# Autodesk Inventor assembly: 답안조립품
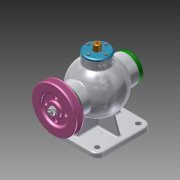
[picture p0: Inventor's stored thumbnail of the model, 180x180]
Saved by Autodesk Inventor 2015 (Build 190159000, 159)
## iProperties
Created: 2025-08
Part Number: 답안조립품
Document SubType Name: Assembly
Designer: USER
Author: USER
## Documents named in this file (16)
- C:\Users\USER\Desktop\750808V1007\답안조립품.iam
- C:\Users\USER\Desktop\750808V1007\본체.ipt
- C:\Users\USER\Desktop\750808V1007\가져온 구성요소\V-벨트풀리\V-벨트풀리.ipt
- C:\Users\USER\Desktop\750808V1007\가져온 구성요소\너트 M8\너트 M8.ipt
- C:\Users\USER\Desktop\750808V1007\가져온 구성요소\뒤커버\뒤커버.ipt
- C:\Users\USER\Desktop\750808V1007\가져온 구성요소\베어링- 6202\베어링- 6202.ipt
- C:\Users\USER\Desktop\750808V1007\가져온 구성요소\볼트 M4 x 12\볼트 M4 x 12.ipt
- C:\Users\USER\Desktop\750808V1007\가져온 구성요소\볼트 M4 x 16\볼트 M4 x 16.ipt
- C:\Users\USER\Desktop\750808V1007\가져온 구성요소\상부커버\상부커버.ipt
- C:\Users\USER\Desktop\750808V1007\가져온 구성요소\슬라이드\슬라이드.ipt
- C:\Users\USER\Desktop\750808V1007\가져온 구성요소\앞커버\앞커버.ipt
- C:\Users\USER\Desktop\750808V1007\가져온 구성요소\오일실 15 30 7\오일실 15 30 7.ipt
- C:\Users\USER\Desktop\750808V1007\가져온 구성요소\칼라\칼라.ipt
- C:\Users\USER\Desktop\750808V1007\가져온 구성요소\키 4 x 4 x 12\키 4 x 4 x 12.ipt
- C:\Users\USER\Desktop\750808V1007\가져온 구성요소\편심축\편심축.ipt
- C:\Users\USER\Desktop\750808V1007\가져온 구성요소\볼트 M4 x 16\볼트 M4 x 16_MIR.ipt
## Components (1 placed, 1 different names)
1. V-벨트풀리:1
